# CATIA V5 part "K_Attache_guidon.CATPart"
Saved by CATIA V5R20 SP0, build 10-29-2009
Part number: Attache_Guidon
Bounding box of the stored display mesh (mm): x -44.93 to 78.335, y -65.546 to 51.536, z -142.351 to 19
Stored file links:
  G:\Khaled_CFAO_2011\ST2M\ST2M_GR1\bmartinez\Khaled\CAD_ThinkMOTION\K_Attache_guidon.CATPart
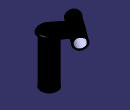
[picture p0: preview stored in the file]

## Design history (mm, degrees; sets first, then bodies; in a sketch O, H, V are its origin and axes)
Body1 (main body)
  Plane1: stored without definition
  Sketch1 on Plane1, origin (0, 0, 0), H (0.8056, -0.5925, 0), V (0, 0, 1)
    circle A1 centre (0, 0) radius 19
    radius A1 = 19
  Pad1: profile Sketch1, direction (-0.5925, -0.8056, 0), length 50, mirrored extent
  DatumCurve1
  Plane2: stored without definition
  Sketch2 on end face of Pad1, origin (-29.6239, -40.2793, 0), H (0.8056, -0.5925, 0), V (0, 0, 1)
    circle A1 centre (0, 0) radius 15.1
    reference projected line E1 through (0, 0) direction (0, -1) from edge of DatumCurve1
    distance A1 E1 = 15.1
  Pocket1: profile Sketch2, direction (0.5925, 0.8056, 0), up to start face of Pad1
  Point1 to Point3: stored without definition
  Sketch3 on Plane2, origin (0, 0, 0), H (0.8056, -0.5925, 0), V (0, 0, 1)
    point P1 (19, 0)
    line L1 (19, 0) -> (60, 0)
    line L2 (60, 0) -> (60, 7.6486)
    line L3 (60, 7.6486) -> (19, 7.6486)
    line L4 (19, 7.6486) -> (19, 0)
    reference projected circle E1 centre (0, 0) radius 19 from edge [face of Pad1 from Sketch1.A1 | end face of Pad1]
    reference projected point E2 (60, 0) from Point3
    coincidence: P1 H, L2 E2
    horizontal: L1 H, L3 H
    vertical: L2 V, L4 V
    tangency: L4 E1
  Pad2: profile Sketch3, direction (-0.5925, -0.8056, 0), length 30, mirrored extent
  Line1: stored without definition
  Plane3: stored without definition
  Plane4: stored without definition
  Pad3: profile face of Pad2 from Sketch3.L4, direction along Line1 reversed, length 2.5
  Point4: stored without definition
  Sketch4 on Plane4, origin (0, 0, 0), H (1, 0, 0), V (0, 1, 0)
    circle A1 centre (48.3352, -35.5487) radius 30
    point P1 (48.3352, -35.5487)
    reference projected point E1 (48.3352, -35.5487) from Point4
    reference projected point E2 (66.1095, -11.3811) from vertex [face of Pad3 | face of Pad2 from Sketch3.L2 | face of Pad3]
    coincidence: P1 E1, A1 E2
  Pad4: profile Sketch4, direction (0, 0, 1), up to face of Pad3
  Point5: stored without definition
  Sketch5 on face of Pad3, origin (0, 0, 7.6486), H (1, 0, 0), V (0, 1, 0)
    circle A1 centre (48.3352, -35.5487) radius 25
    point P1 (48.3352, -35.5487)
    reference projected point E1 (48.3352, -35.5487) from Point5
    radius A1 = 25
    coincidence: P1 E1
  Pad5: profile Sketch5, direction (0, 0, -1), length 150
  Sketch6 on end face of Pad5, origin (0, 0, -142.3514), H (1, 0, 0), V (0, -1, 0)
    circle A1 centre (48.3352, 35.5487) radius 20
    reference projected circle E1 centre (48.3352, 35.5487) radius 25 from edge [face of Pad2 | face of Pad5 from Sketch5.A1]
    radius A1 = 20
    concentricity: E1 A1
  Pocket2: profile Sketch6, direction (0, 0, 1), length 120
  Fillet1: radius 5, on face of Pad5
